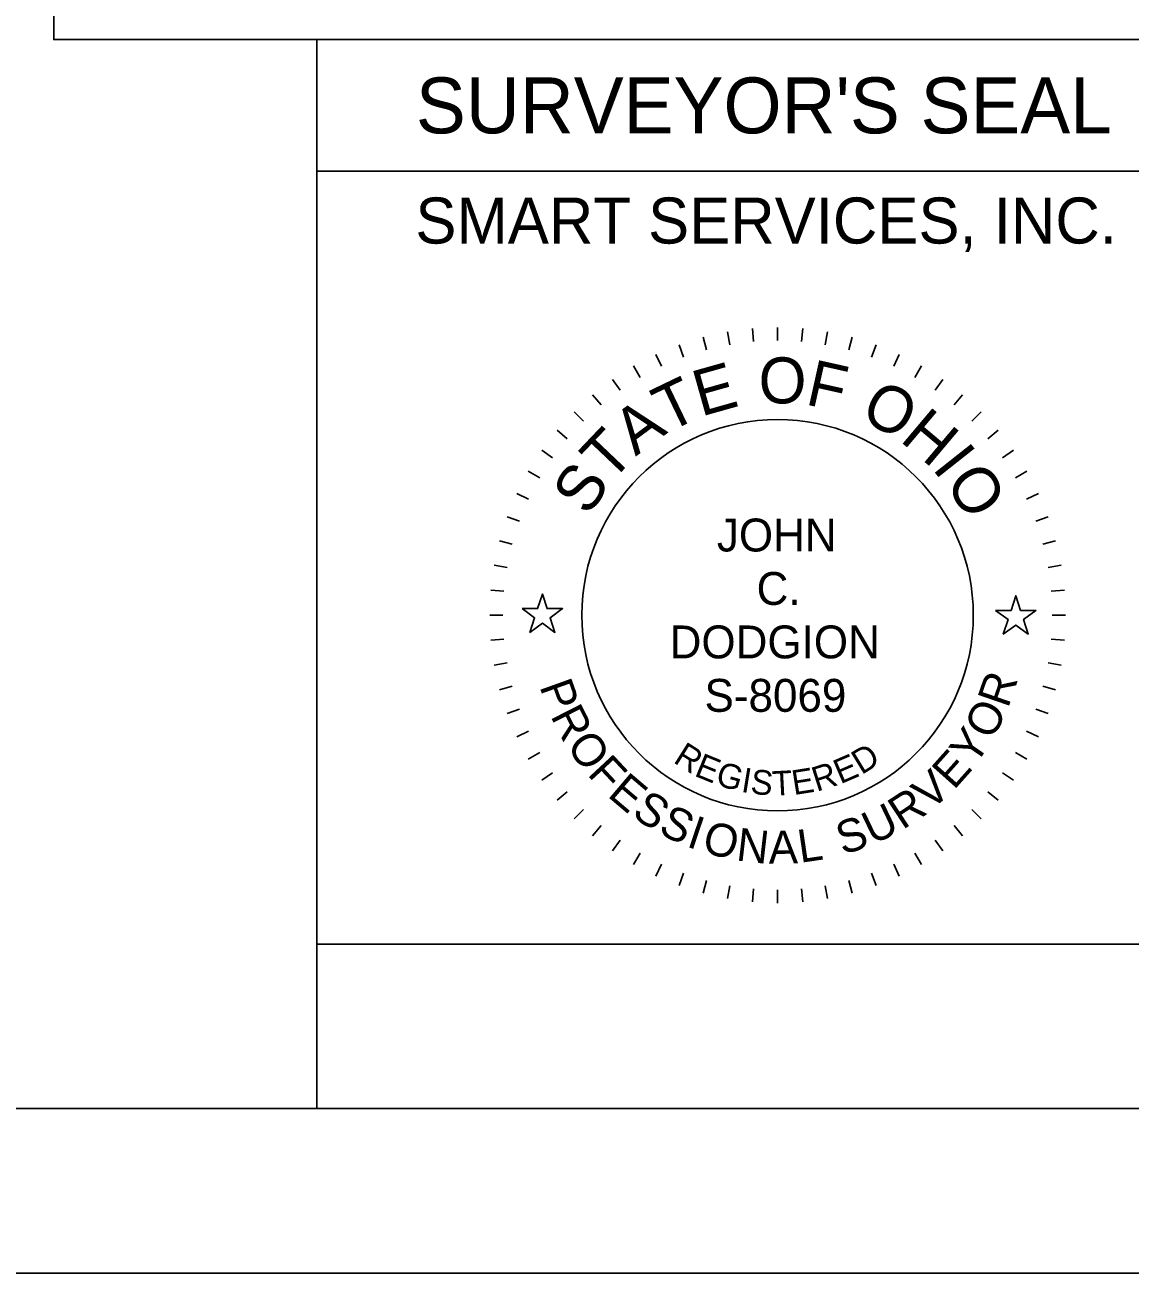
# Model space of a CAD drawing. Extents: x 0 to 34, y 0 to 22.
# Drawn here: x 28.312 to 31.671, y 0 to 3.795 of the extents above; entities that cross this region are included whole.
import ezdxf

# ---------------------------------------------------------------- set-up
doc = ezdxf.new("R2010")
doc.units = 0
for name, color, linetype in [('SH_Border', 7, 'Continuous'), ('SH_Cut_Line', 7, 'Continuous'), ('SH_Data', 7, 'Continuous')]:
    doc.layers.add(name, color=color, linetype=linetype)

msp = doc.modelspace()

# ---------------------------------------------------------------- linework, layer by layer
at = {"layer": 'SH_Border'}
msp.add_lwpolyline([(1.5, 21.5), (33.5, 21.5), (33.5, 0.5), (1.5, 0.5)], close=True, dxfattribs=at)
at = {"layer": 'SH_Cut_Line'}
msp.add_lwpolyline([(0, 0), (34, 0), (34, 22), (0, 22)], close=True, dxfattribs=at)
at = {"layer": 'SH_Data'}
for p, q in [((32, 3.75), (29.2, 3.75)), ((29.2, 3.75), (29.2, 0.5)), ((32, 3.35), (29.2, 3.35)), ((30.4481, 2.8617), (30.455, 2.8223)), ((30.5237, 2.8717), (30.5272, 2.8318)), ((30.6, 2.875), (30.6, 2.835)), ((30.6763, 2.8717), (30.6728, 2.8318)), ((30.7519, 2.8617), (30.745, 2.8223)), ((30.3007, 2.8222), (30.3144, 2.7846)), ((30.3735, 2.8452), (30.3839, 2.8065)), ((30.8265, 2.8452), (30.8161, 2.8065)), ((30.8993, 2.8222), (30.8856, 2.7846)), ((30.2302, 2.793), (30.2471, 2.7568)), ((30.9698, 2.793), (30.9529, 2.7568)), ((30.1625, 2.7578), (30.1825, 2.7231)), ((31.0375, 2.7578), (31.0175, 2.7231)), ((30.0981, 2.7168), (30.1211, 2.684)), ((31.1019, 2.7168), (31.0789, 2.684)), ((30.0376, 2.6703), (30.0633, 2.6396)), ((31.1624, 2.6703), (31.1367, 2.6396)), ((29.9813, 2.6187), (30.0096, 2.5904)), ((31.2187, 2.6187), (31.1904, 2.5904)), ((29.9297, 2.5624), (29.9604, 2.5367)), ((31.2703, 2.5624), (31.2396, 2.5367)), ((29.8832, 2.5019), (29.916, 2.4789)), ((31.3168, 2.5019), (31.284, 2.4789)), ((29.8422, 2.4375), (29.8769, 2.4175)), ((31.3578, 2.4375), (31.3231, 2.4175)), ((29.807, 2.3698), (29.8432, 2.3529)), ((31.393, 2.3698), (31.3568, 2.3529)), ((29.7778, 2.2993), (29.8154, 2.2856)), ((31.4222, 2.2993), (31.3846, 2.2856)), ((29.7548, 2.2265), (29.7935, 2.2161)), ((31.4452, 2.2265), (31.4065, 2.2161)), ((29.7383, 2.1519), (29.7777, 2.145)), ((31.4617, 2.1519), (31.4223, 2.145)), ((29.7283, 2.0763), (29.7682, 2.0728)), ((31.4717, 2.0763), (31.4318, 2.0728)), ((29.725, 2), (29.765, 2)), ((31.475, 2), (31.435, 2)), ((29.7283, 1.9237), (29.7682, 1.9272)), ((31.4717, 1.9237), (31.4318, 1.9272)), ((29.7383, 1.8481), (29.7777, 1.855)), ((31.4617, 1.8481), (31.4223, 1.855)), ((29.7548, 1.7735), (29.7935, 1.7839)), ((31.4452, 1.7735), (31.4065, 1.7839)), ((29.7778, 1.7007), (29.8154, 1.7144)), ((31.4222, 1.7007), (31.3846, 1.7144)), ((29.807, 1.6302), (29.8432, 1.6471)), ((31.393, 1.6302), (31.3568, 1.6471)), ((29.8422, 1.5625), (29.8769, 1.5825)), ((31.3578, 1.5625), (31.3231, 1.5825)), ((29.8832, 1.4981), (29.916, 1.5211)), ((31.3168, 1.4981), (31.284, 1.5211)), ((29.9297, 1.4376), (29.9604, 1.4633)), ((31.2703, 1.4376), (31.2396, 1.4633)), ((29.9813, 1.3813), (30.0096, 1.4096)), ((31.2187, 1.3813), (31.1904, 1.4096)), ((30.0376, 1.3297), (30.0633, 1.3604)), ((31.1624, 1.3297), (31.1367, 1.3604)), ((30.0981, 1.2832), (30.1211, 1.316)), ((31.1019, 1.2832), (31.0789, 1.316)), ((30.1625, 1.2422), (30.1825, 1.2769)), ((31.0375, 1.2422), (31.0175, 1.2769)), ((30.2302, 1.207), (30.2471, 1.2432)), ((30.3007, 1.1778), (30.3144, 1.2154)), ((30.8993, 1.1778), (30.8856, 1.2154)), ((30.9698, 1.207), (30.9529, 1.2432)), ((30.3735, 1.1548), (30.3839, 1.1935)), ((30.4481, 1.1383), (30.455, 1.1777)), ((30.7519, 1.1383), (30.745, 1.1777)), ((30.8265, 1.1548), (30.8161, 1.1935)), ((30.5237, 1.1283), (30.5272, 1.1682)), ((30.6, 1.125), (30.6, 1.165)), ((30.6763, 1.1283), (30.6728, 1.1682)), ((32, 0.5), (29.2, 0.5))]:
    msp.add_line(p, q, dxfattribs=at)
for points in [[(28.4, 7.85), (32, 7.85), (32, 3.75), (28.4, 3.75)], [(29.8236, 2.02), (29.8705, 2.02), (29.885, 2.0645), (29.8995, 2.02), (29.9464, 2.02), (29.9085, 1.9924), (29.923, 1.9478), (29.885, 1.9754), (29.847, 1.9478), (29.8615, 1.9924)], [(31.2627, 2.0146), (31.3096, 2.0146), (31.3241, 2.0591), (31.3386, 2.0146), (31.3855, 2.0146), (31.3476, 1.987), (31.3621, 1.9424), (31.3241, 1.97), (31.2861, 1.9424), (31.3006, 1.987)], [(32, 0.5), (32, 1), (29.2, 1), (29.2, 0.5)]]:
    msp.add_lwpolyline(points, close=True, dxfattribs=at)
msp.add_circle((30.6, 2), 0.595, dxfattribs=at)

# ---------------------------------------------------------------- texts
for s, height, p in [("SURVEYOR'S SEAL", 0.17, (29.5006, 3.465)), ('SMART SERVICES, INC.', 0.14, (29.4991, 3.13)), ('JOHN', 0.1, (30.4155, 2.1938)), ('C.', 0.1, (30.5362, 2.0313)), ('DODGION', 0.1, (30.2719, 1.8688)), ('S-8069', 0.1, (30.3779, 1.7063))]:
    msp.add_text(s, height=height, dxfattribs=at).set_placement(p)
for s, height, rotation, p in [('O', 0.14, 359.7812, (30.542, 2.6442)), ('F', 0.14, 347.4362, (30.6811, 2.6417)), ('E', 0.14, 15.7571, (30.3669, 2.6034)), ('T', 0.14, 25.7167, (30.2661, 2.554)), ('O', 0.14, 332.2586, (30.8463, 2.5981)), ('A', 0.14, 36.4747, (30.1685, 2.4819)), ('H', 0.14, 319.9136, (30.9684, 2.5316)), ('T', 0.14, 46.4344, (30.0917, 2.4)), ('I', 0.14, 308.367, (31.0674, 2.4471)), ('S', 0.14, 57.1924, (30.026, 2.2981)), ('O', 0.14, 303.1491, (31.1061, 2.4028)), ('R', 0.1, 70.983, (31.3003, 1.7149)), ('P', 0.1, 289.7431, (29.8754, 1.7839)), ('R', 0.1, 296.9802, (29.9084, 1.6943)), ('O', 0.1, 62.7428, (31.2522, 1.6174)), ('O', 0.1, 304.7158, (29.9558, 1.604)), ('Y', 0.1, 55.5058, (31.1988, 1.5383)), ('R', 0.075, 327.8239, (30.2801, 1.554)), ('D', 0.075, 31.466, (30.855, 1.5136)), ('F', 0.1, 312.956, (30.0192, 1.5158)), ('E', 0.075, 337.7777, (30.3439, 1.5128)), ('E', 0.075, 23.3052, (30.7909, 1.4856)), ('E', 0.1, 48.2687, (31.1359, 1.4666)), ('E', 0.1, 319.6885, (30.08, 1.451)), ('G', 0.075, 344.2727, (30.4082, 1.4848)), ('I', 0.075, 350.6464, (30.4868, 1.4634)), ('S', 0.075, 353.7858, (30.5155, 1.4581)), ('T', 0.075, 3.0061, (30.5852, 1.4505)), ('E', 0.075, 8.9826, (30.6492, 1.453)), ('R', 0.075, 17.6836, (30.7187, 1.4627)), ('V', 0.1, 41.0316, (31.0644, 1.4033)), ('S', 0.1, 326.9255, (30.1533, 1.3899)), ('R', 0.1, 33.296, (30.9799, 1.3462)), ('S', 0.1, 334.1626, (30.2337, 1.3385)), ('U', 0.1, 25.5604, (30.8884, 1.301)), ('I', 0.1, 341.3997, (30.32, 1.2976)), ('O', 0.1, 345.1351, (30.3663, 1.2809)), ('S', 0.1, 18.3234, (30.7981, 1.2703)), ('N', 0.1, 353.3752, (30.4718, 1.2548)), ('A', 0.1, 1.1108, (30.5733, 1.2443)), ('L', 0.1, 8.3479, (30.6687, 1.247))]:
    msp.add_text(s, height=height, rotation=rotation, dxfattribs=at).set_placement(p)

doc.saveas('drawing.dxf')
